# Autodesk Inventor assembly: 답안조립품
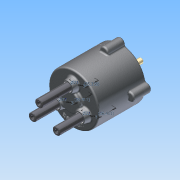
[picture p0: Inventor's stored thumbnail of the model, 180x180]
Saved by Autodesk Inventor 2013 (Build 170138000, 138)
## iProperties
Created: 2014-07
Part Number: 답안조립품
Document SubType Name: Assembly
Designer: SEMTLE01_MAIN
Author: SEMTLE01_MAIN
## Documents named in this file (14)
- C:\Users\성경\Desktop\Inventor_강성경\답안조립품.iam
- C:\Users\성경\Desktop\Inventor_강성경\몸체.ipt
- C:\Users\성경\Desktop\Inventor_강성경\M5x0.5x20.ipt
- C:\Users\성경\Desktop\Inventor_강성경\베어링 NA 4900.ipt
- C:\Users\성경\Desktop\Inventor_강성경\오일실.ipt
- C:\Users\성경\Desktop\Inventor_강성경\커버.ipt
- C:\Users\성경\Desktop\Inventor_강성경\멈춤링 10 x 1.ipt
- C:\Users\성경\Desktop\Inventor_강성경\멈춤링 22 x 1.2.ipt
- C:\Users\성경\Desktop\Inventor_강성경\메인 축.ipt
- C:\Users\성경\Desktop\Inventor_강성경\판캠.ipt
- C:\Users\성경\Desktop\Inventor_강성경\슬라이드 축.ipt
- C:\Users\성경\Desktop\Inventor_강성경\가변스프링01.ipt
- C:\Users\성경\Desktop\Inventor_강성경\가변스프링02.ipt
- C:\Users\성경\Desktop\Inventor_강성경\가변스프링03.ipt
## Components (7 placed, 4 different names)
1. 가변스프링01:1
2. 가변스프링02:1
3. 가변스프링03:1
4. M5x0.5x20:1
5. M5x0.5x20:2
6. M5x0.5x20:3
7. M5x0.5x20:4
